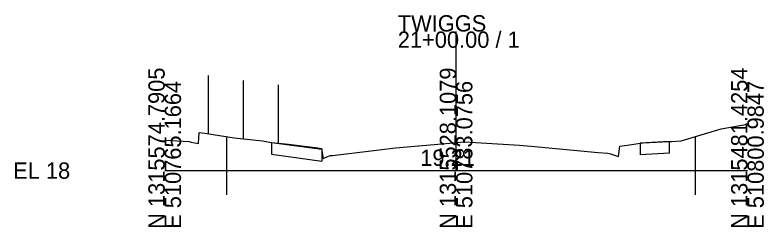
# Model space of a CAD drawing. Extents: x -842 to 387, y -2205 to 8329.
# Drawn here: x -841.5 to -713, y -2205.4 to -2169 of the extents above; entities that cross this region are included whole.
import ezdxf

# ---------------------------------------------------------------- set-up
doc = ezdxf.new("R2010")
doc.units = 0
for name, color, linetype in [('CurbBack', 7, 'Continuous'), ('Miscellaneous6', 7, 'Continuous'), ('Sidewalk_ex', 7, 'Continuous'), ('Sidewalk_px', 7, 'Continuous'), ('TextXSElev_ex', 7, 'Continuous'), ('XSCell', 7, 'Continuous'), ('XSGrdLine_ex', 7, 'Continuous')]:
    doc.layers.add(name, color=color, linetype=linetype)

msp = doc.modelspace()

# ---------------------------------------------------------------- linework, layer by layer
at = {"layer": 'CurbBack'}
msp.add_line((-796.34, -2180.99), (-796.34, -2190.99), dxfattribs=at)
at = {"layer": 'Miscellaneous6'}
for p, q in [((-805.19, -2189.87), (-805.19, -2199.87)), ((-724.81, -2189.87), (-724.81, -2199.87))]:
    msp.add_line(p, q, dxfattribs=at)
at = {"layer": 'Sidewalk_ex'}
for p, q in [((-797.49, -2190.86), (-788.87, -2192.05)), ((-797.49, -2190.86), (-797.49, -2192.88)), ((-729.24, -2190.72), (-734.22, -2190.98)), ((-734.22, -2190.98), (-734.22, -2192.99)), ((-729.24, -2190.72), (-729.24, -2192.73)), ((-788.87, -2192.05), (-788.87, -2194.07)), ((-729.24, -2192.73), (-734.22, -2192.99)), ((-797.49, -2192.88), (-788.87, -2194.07))]:
    msp.add_line(p, q, dxfattribs=at)
at = {"layer": 'Sidewalk_px'}
for p, q in [((-808.35, -2179.37), (-808.35, -2189.37)), ((-808.35, -2179.37), (-808.35, -2189.37)), ((-802.35, -2180.24), (-802.35, -2190.24)), ((-802.35, -2180.24), (-802.35, -2190.24))]:
    msp.add_line(p, q, dxfattribs=at)
at = {"layer": 'XSCell'}
for p, q in [((-765.82, -2195.7), (-765.82, -2171.82)), ((-815.82, -2195.7), (-765.82, -2195.7)), ((-765.82, -2195.7), (-715.82, -2195.7))]:
    msp.add_line(p, q, dxfattribs=at)
at = {"layer": 'XSGrdLine_ex'}
msp.add_lwpolyline([(-815.82, -2190.49), (-811.6, -2190.73), (-811.28, -2190.82), (-810.01, -2191.04), (-809.92, -2189.15), (-809.37, -2189.21), (-808.93, -2189.28), (-803.92, -2190.07), (-799.04, -2190.6), (-797.49, -2190.86), (-794.56, -2191.19), (-789.52, -2191.81), (-788.89, -2191.88), (-788.64, -2193.64), (-787.72, -2193.24), (-787.34, -2193.1), (-787.01, -2193.12), (-779.04, -2192.14), (-776.2, -2191.79), (-766.92, -2190.97), (-765.82, -2190.87), (-764.33, -2190.74), (-754.93, -2191.35), (-752.95, -2191.48), (-741.43, -2192.57), (-739.78, -2192.73), (-739.33, -2192.82), (-738.65, -2193.05), (-737.96, -2193.28), (-737.73, -2191.51), (-735.66, -2191.2), (-734.22, -2190.98), (-733.71, -2190.95), (-729.24, -2190.72), (-728.85, -2190.7), (-727.18, -2190.58), (-720.32, -2188.52), (-715.82, -2187.74)], dxfattribs=at)

# ---------------------------------------------------------------- texts
at = {"layer": 'TextXSElev_ex'}
msp.add_text('19.21', height=2.8, dxfattribs=at).set_placement((-771.96, -2194.9))
at = {"layer": 'XSCell'}
for s, p in [('TWIGGS', (-775.82, -2171.82)), ('21+00.00 / 1', (-775.82, -2174.62)), ('EL 18', (-841.82, -2197.1))]:
    msp.add_text(s, height=2.8, dxfattribs=at).set_placement(p)
for s, p in [('N 1315574.7905', (-815.82, -2205.7)), ('N 1315528.1079', (-765.82, -2205.7)), ('N 1315481.4254', (-715.82, -2205.7)), ('E 510765.1664', (-813.02, -2205.7)), ('E 510783.0756', (-763.02, -2205.7)), ('E 510800.9847', (-713.02, -2205.7))]:
    msp.add_text(s, height=2.8, rotation=90, dxfattribs=at).set_placement(p)

doc.saveas('drawing.dxf')
